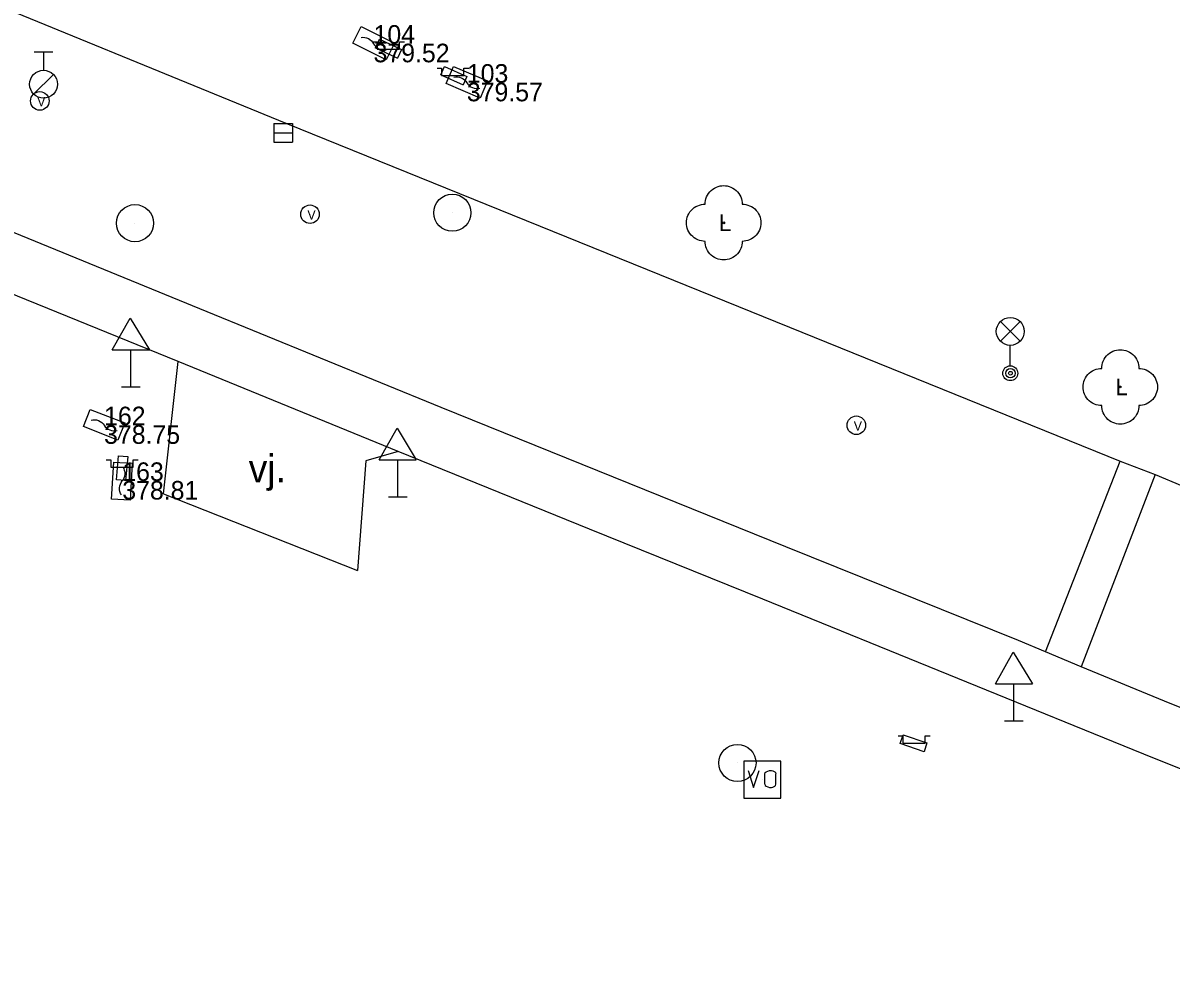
# Model space of a CAD drawing. Extents: x -836568 to -836015, y -1070547 to -1070212.
# Drawn here: x -836329.46 to -836298.57, y -1070441.99 to -1070416.28 of the extents above; entities that cross this region are included whole.
import ezdxf

# ---------------------------------------------------------------- set-up
doc = ezdxf.new("R2010")
doc.units = 0
for name, color, linetype in [('BodPole_mer', 7, 'Continuous'), ('BodPole_popis', 7, 'Continuous'), ('Doprava_body', 7, 'Continuous'), ('Doprava_hranice', 7, 'Continuous'), ('Doprava_kody', 7, 'Continuous'), ('PovrZnIS_body', 7, 'Continuous'), ('PovrZnIS_hranice', 7, 'Continuous'), ('PovrZnIS_kody', 7, 'Continuous'), ('Zelen_body', 7, 'Continuous')]:
    doc.layers.add(name, color=color, linetype=linetype)

msp = doc.modelspace()

# ---------------------------------------------------------------- linework, layer by layer
at = {"layer": 'BodPole_mer'}
for p, q in [((-836320.03, -1070416.84), (-836320.03, -1070416.84)), ((-836319.87, -1070416.72), (-836319.87, -1070416.72)), ((-836319.87, -1070416.72), (-836319.87, -1070416.72)), ((-836319.98, -1070416.95), (-836319.98, -1070416.95)), ((-836319.98, -1070416.95), (-836319.98, -1070416.95)), ((-836319.28, -1070417), (-836319.28, -1070417)), ((-836319.28, -1070417), (-836319.28, -1070417)), ((-836319.39, -1070417.23), (-836319.39, -1070417.23)), ((-836319.39, -1070417.23), (-836319.39, -1070417.23)), ((-836318.12, -1070417.45), (-836318.12, -1070417.45)), ((-836318.12, -1070417.45), (-836318.12, -1070417.45)), ((-836318.22, -1070417.68), (-836318.22, -1070417.68)), ((-836318.22, -1070417.68), (-836318.22, -1070417.68)), ((-836317.52, -1070417.72), (-836317.52, -1070417.72)), ((-836317.52, -1070417.72), (-836317.52, -1070417.72)), ((-836328.91, -1070417.93), (-836328.91, -1070417.93)), ((-836317.62, -1070417.95), (-836317.62, -1070417.95)), ((-836317.62, -1070417.95), (-836317.62, -1070417.95)), ((-836317.52, -1070417.89), (-836317.52, -1070417.89)), ((-836329.01, -1070418.38), (-836329.01, -1070418.38)), ((-836322.39, -1070418.98), (-836322.39, -1070418.98)), ((-836322.46, -1070419.24), (-836322.46, -1070419.24)), ((-836321.74, -1070421.43), (-836321.74, -1070421.43)), ((-836317.91, -1070421.39), (-836317.91, -1070421.39)), ((-836326.45, -1070421.67), (-836326.45, -1070421.67)), ((-836310.61, -1070421.66), (-836310.61, -1070421.66)), ((-836329.32, -1070422.08), (-836329.32, -1070422.08)), ((-836311.25, -1070423.49), (-836311.25, -1070423.49)), ((-836324.7, -1070423.98), (-836324.7, -1070423.98)), ((-836325.29, -1070425.39), (-836325.29, -1070425.39)), ((-836302.9, -1070425.71), (-836302.9, -1070425.71)), ((-836326.56, -1070426.08), (-836326.56, -1070426.08)), ((-836299.94, -1070426.08), (-836299.94, -1070426.08)), ((-836318.21, -1070426.63), (-836318.21, -1070426.63)), ((-836327.28, -1070427.11), (-836327.28, -1070427.11)), ((-836307.04, -1070427.11), (-836307.04, -1070427.11)), ((-836326.89, -1070427.93), (-836326.89, -1070427.93)), ((-836326.89, -1070427.93), (-836326.89, -1070427.93)), ((-836326.64, -1070427.95), (-836326.64, -1070427.95)), ((-836326.64, -1070427.95), (-836326.64, -1070427.95)), ((-836319.37, -1070427.82), (-836319.37, -1070427.82)), ((-836320.24, -1070428.07), (-836320.24, -1070428.07)), ((-836299.94, -1070428.08), (-836299.94, -1070428.08)), ((-836326.95, -1070428.58), (-836326.95, -1070428.58)), ((-836326.95, -1070428.58), (-836326.95, -1070428.58)), ((-836326.79, -1070428.61), (-836326.79, -1070428.61)), ((-836326.7, -1070428.6), (-836326.7, -1070428.6)), ((-836326.7, -1070428.6), (-836326.7, -1070428.6)), ((-836313.57, -1070428.51), (-836313.57, -1070428.51)), ((-836299, -1070428.44), (-836299, -1070428.44)), ((-836325.68, -1070428.96), (-836325.68, -1070428.96)), ((-836319.38, -1070429.04), (-836319.38, -1070429.04)), ((-836314.22, -1070429.91), (-836314.22, -1070429.91)), ((-836308.94, -1070430.38), (-836308.94, -1070430.38)), ((-836320.46, -1070431.02), (-836320.46, -1070431.02)), ((-836309.56, -1070431.79), (-836309.56, -1070431.79)), ((-836302.68, -1070432.9), (-836302.68, -1070432.9)), ((-836301.95, -1070433.21), (-836301.95, -1070433.21)), ((-836300.99, -1070433.61), (-836300.99, -1070433.61)), ((-836298.75, -1070434.54), (-836298.75, -1070434.54)), ((-836302.8, -1070435.07), (-836302.8, -1070435.07)), ((-836305.86, -1070435.68), (-836305.86, -1070435.68)), ((-836305.86, -1070435.68), (-836305.86, -1070435.68)), ((-836305.78, -1070435.44), (-836305.78, -1070435.44)), ((-836305.78, -1070435.44), (-836305.78, -1070435.44)), ((-836305.14, -1070435.66), (-836305.14, -1070435.66)), ((-836305.14, -1070435.66), (-836305.14, -1070435.66)), ((-836305.22, -1070435.9), (-836305.22, -1070435.9)), ((-836305.22, -1070435.9), (-836305.22, -1070435.9)), ((-836310.24, -1070436.2), (-836310.24, -1070436.2)), ((-836299.06, -1070436.06), (-836299.06, -1070436.06)), ((-836309.57, -1070436.65), (-836309.57, -1070436.65))]:
    msp.add_line(p, q, dxfattribs=at)
at = {"layer": 'Doprava_body'}
for p, q in [((-836327.06, -1070425.08), (-836326.579, -1070424.226)), ((-836326.579, -1070424.226), (-836326.06, -1070425.08)), ((-836327.06, -1070425.08), (-836326.06, -1070425.08)), ((-836326.56, -1070426.08), (-836326.56, -1070425.08)), ((-836326.81, -1070426.08), (-836326.31, -1070426.08)), ((-836319.88, -1070428.04), (-836319.399, -1070427.186)), ((-836319.399, -1070427.186), (-836318.88, -1070428.04)), ((-836319.88, -1070428.04), (-836318.88, -1070428.04)), ((-836319.38, -1070429.04), (-836319.38, -1070428.04)), ((-836319.63, -1070429.04), (-836319.13, -1070429.04)), ((-836303.3, -1070434.07), (-836302.819, -1070433.216)), ((-836302.819, -1070433.216), (-836302.3, -1070434.07)), ((-836303.3, -1070434.07), (-836302.3, -1070434.07)), ((-836302.8, -1070435.07), (-836302.8, -1070434.07)), ((-836303.05, -1070435.07), (-836302.55, -1070435.07))]:
    msp.add_line(p, q, dxfattribs=at)
at = {"layer": 'Doprava_hranice'}
for p, q in [((-836325.68, -1070428.96), (-836325.29, -1070425.39)), ((-836301.95, -1070433.21), (-836299.94, -1070428.08)), ((-836299, -1070428.44), (-836300.99, -1070433.61)), ((-836325.68, -1070428.96), (-836320.46, -1070431.02))]:
    msp.add_line(p, q, dxfattribs=at)
for points in [[(-836294.78, -1070436.14), (-836298.75, -1070434.54), (-836300.99, -1070433.61), (-836301.95, -1070433.21), (-836302.68, -1070432.9), (-836308.94, -1070430.38), (-836313.57, -1070428.51), (-836318.21, -1070426.63), (-836324.7, -1070423.98), (-836329.32, -1070422.08), (-836333.96, -1070420.19), (-836342.84, -1070416.58), (-836353.67, -1070412.18), (-836369.06, -1070405.92), (-836381.28, -1070400.95), (-836385.01, -1070399.41), (-836387.75, -1070398.25), (-836390.49, -1070397.04), (-836393.21, -1070395.81), (-836395.03, -1070394.97), (-836397.75, -1070393.68), (-836399.24, -1070392.97)], [(-836351.68, -1070407.06), (-836340.95, -1070411.41), (-836331.95, -1070415.06), (-836322.39, -1070418.98), (-836311.25, -1070423.49), (-836299.94, -1070428.08), (-836299, -1070428.44), (-836298.27, -1070428.74)], [(-836282.83, -1070440.54), (-836283.39, -1070441.99), (-836288.97, -1070439.98), (-836292.82, -1070438.51), (-836295.89, -1070437.33), (-836299.06, -1070436.06), (-836309.56, -1070431.79), (-836314.22, -1070429.91), (-836319.37, -1070427.82), (-836325.29, -1070425.39), (-836329.9, -1070423.52), (-836331.04, -1070426.22), (-836335.67, -1070424.36), (-836334.55, -1070421.64), (-836343.54, -1070417.97), (-836354.29, -1070413.6)], [(-836319.37, -1070427.82), (-836320.24, -1070428.07), (-836320.46, -1070431.02)]]:
    msp.add_lwpolyline(points, dxfattribs=at)
at = {"layer": 'PovrZnIS_body'}
for p, q in [((-836320.588, -1070416.827), (-836320.365, -1070416.38)), ((-836320.365, -1070416.38), (-836319.47, -1070416.827)), ((-836319.694, -1070417.274), (-836320.588, -1070416.827)), ((-836319.47, -1070416.827), (-836319.694, -1070417.274)), ((-836329.16, -1070417.055), (-836328.66, -1070417.055)), ((-836328.91, -1070417.055), (-836328.91, -1070417.555)), ((-836318.078, -1070417.911), (-836317.882, -1070417.451)), ((-836317.882, -1070417.451), (-836316.962, -1070417.843)), ((-836328.645, -1070417.665), (-836329.175, -1070418.195)), ((-836317.158, -1070418.303), (-836318.078, -1070417.911)), ((-836316.962, -1070417.843), (-836317.158, -1070418.303)), ((-836322.71, -1070418.99), (-836322.21, -1070418.99)), ((-836322.71, -1070418.99), (-836322.71, -1070419.49)), ((-836322.21, -1070418.99), (-836322.21, -1070419.49)), ((-836322.71, -1070419.24), (-836322.21, -1070419.24)), ((-836322.71, -1070419.49), (-836322.21, -1070419.49)), ((-836303.165, -1070424.85), (-836302.635, -1070424.32)), ((-836303.165, -1070424.32), (-836302.635, -1070424.85)), ((-836302.9, -1070425.51), (-836302.9, -1070424.96)), ((-836327.837, -1070427.147), (-836327.654, -1070426.682)), ((-836327.654, -1070426.682), (-836326.723, -1070427.047)), ((-836326.723, -1070427.047), (-836326.906, -1070427.513)), ((-836326.906, -1070427.513), (-836327.837, -1070427.147)), ((-836327.082, -1070429.098), (-836327.021, -1070428.1)), ((-836327.021, -1070428.1), (-836326.522, -1070428.13)), ((-836326.522, -1070428.13), (-836326.583, -1070429.128)), ((-836326.583, -1070429.128), (-836327.082, -1070429.098)), ((-836309.07, -1070436.15), (-836310.07, -1070436.15)), ((-836310.07, -1070436.15), (-836310.07, -1070437.15)), ((-836309.07, -1070437.15), (-836309.07, -1070436.15)), ((-836310.07, -1070437.15), (-836309.07, -1070437.15))]:
    msp.add_line(p, q, dxfattribs=at)
for points in [[(-836320.367, -1070416.671), (-836320.319, -1070416.667), (-836320.269, -1070416.669), (-836320.219, -1070416.68), (-836320.17, -1070416.7), (-836320.126, -1070416.727), (-836320.087, -1070416.76), (-836320.055, -1070416.799), (-836320.03, -1070416.84)], [(-836320.03, -1070416.84), (-836320.005, -1070416.881), (-836319.973, -1070416.919), (-836319.935, -1070416.953), (-836319.89, -1070416.98), (-836319.842, -1070416.999), (-836319.792, -1070417.01), (-836319.742, -1070417.013), (-836319.695, -1070417.008)], [(-836317.867, -1070417.742), (-836317.819, -1070417.735), (-836317.769, -1070417.734), (-836317.718, -1070417.742), (-836317.669, -1070417.759), (-836317.623, -1070417.783), (-836317.582, -1070417.814), (-836317.547, -1070417.85), (-836317.52, -1070417.89)], [(-836317.52, -1070417.89), (-836317.493, -1070417.93), (-836317.459, -1070417.966), (-836317.418, -1070417.997), (-836317.372, -1070418.021), (-836317.323, -1070418.037), (-836317.272, -1070418.045), (-836317.222, -1070418.045), (-836317.175, -1070418.037)], [(-836327.63, -1070426.972), (-836327.583, -1070426.963), (-836327.533, -1070426.961), (-836327.482, -1070426.968), (-836327.432, -1070426.983), (-836327.386, -1070427.006), (-836327.344, -1070427.036), (-836327.308, -1070427.071), (-836327.28, -1070427.11)], [(-836327.28, -1070427.11), (-836327.252, -1070427.149), (-836327.216, -1070427.184), (-836327.175, -1070427.214), (-836327.128, -1070427.237), (-836327.079, -1070427.252), (-836327.028, -1070427.258), (-836326.978, -1070427.256), (-836326.931, -1070427.247)], [(-836326.79, -1070428.61), (-836326.762, -1070428.571), (-836326.739, -1070428.527), (-836326.724, -1070428.478), (-836326.716, -1070428.427), (-836326.717, -1070428.375), (-836326.727, -1070428.324), (-836326.744, -1070428.278), (-836326.767, -1070428.236)], [(-836326.813, -1070428.986), (-836326.836, -1070428.944), (-836326.853, -1070428.897), (-836326.863, -1070428.846), (-836326.864, -1070428.794), (-836326.856, -1070428.743), (-836326.841, -1070428.694), (-836326.818, -1070428.649), (-836326.79, -1070428.61)], [(-836309.955, -1070436.407), (-836309.805, -1070436.857)], [(-836309.805, -1070436.857), (-836309.655, -1070436.407)], [(-836309.503, -1070436.491), (-836309.493, -1070436.461), (-836309.47, -1070436.438), (-836309.424, -1070436.417), (-836309.379, -1070436.407), (-836309.319, -1070436.407), (-836309.29, -1070436.415), (-836309.233, -1070436.44), (-836309.213, -1070436.461), (-836309.203, -1070436.491)], [(-836309.503, -1070436.772), (-836309.503, -1070436.491)], [(-836309.203, -1070436.772), (-836309.203, -1070436.491)], [(-836309.503, -1070436.772), (-836309.493, -1070436.803), (-836309.47, -1070436.825), (-836309.424, -1070436.847), (-836309.379, -1070436.857), (-836309.319, -1070436.857), (-836309.29, -1070436.849), (-836309.233, -1070436.823), (-836309.213, -1070436.803), (-836309.203, -1070436.772)]]:
    msp.add_lwpolyline(points, dxfattribs=at)
for centre, radius in [((-836328.91, -1070417.93), 0.375), ((-836329.01, -1070418.38), 0.25), ((-836317.91, -1070421.39), 0.5), ((-836326.45, -1070421.67), 0.5), ((-836321.74, -1070421.43), 0.25), ((-836307.04, -1070427.11), 0.25), ((-836310.24, -1070436.2), 0.5)]:
    msp.add_circle(centre, radius, dxfattribs=at)
for centre, major_axis in [((-836302.9, -1070424.585), (0.375, 0)), ((-836302.9, -1070425.71), (0.2, 0)), ((-836302.896, -1070425.71), (0.125, 0)), ((-836302.896, -1070425.71), (0.05, 0))]:
    msp.add_ellipse(centre, major_axis=major_axis, ratio=0.999998, dxfattribs=at)
at = {"layer": 'PovrZnIS_hranice'}
for p, q in [((-836319.98, -1070416.95), (-836319.39, -1070417.23)), ((-836319.98, -1070416.95), (-836319.39, -1070417.23)), ((-836318.22, -1070417.68), (-836317.62, -1070417.95)), ((-836318.22, -1070417.68), (-836317.62, -1070417.95)), ((-836326.64, -1070427.95), (-836326.7, -1070428.6)), ((-836326.64, -1070427.95), (-836326.7, -1070428.6)), ((-836305.78, -1070435.44), (-836305.14, -1070435.66)), ((-836305.78, -1070435.44), (-836305.14, -1070435.66))]:
    msp.add_line(p, q, dxfattribs=at)
for points in [[(-836319.98, -1070416.95), (-836319.87, -1070416.72), (-836319.28, -1070417), (-836319.39, -1070417.23)], [(-836319.98, -1070416.95), (-836319.87, -1070416.72), (-836319.28, -1070417), (-836319.39, -1070417.23)], [(-836318.22, -1070417.68), (-836318.12, -1070417.45), (-836317.52, -1070417.72), (-836317.62, -1070417.95)], [(-836318.22, -1070417.68), (-836318.12, -1070417.45), (-836317.52, -1070417.72), (-836317.62, -1070417.95)], [(-836326.7, -1070428.6), (-836326.95, -1070428.58), (-836326.89, -1070427.93), (-836326.64, -1070427.95)], [(-836326.7, -1070428.6), (-836326.95, -1070428.58), (-836326.89, -1070427.93), (-836326.64, -1070427.95)], [(-836305.14, -1070435.66), (-836305.22, -1070435.9), (-836305.86, -1070435.68), (-836305.78, -1070435.44)], [(-836305.14, -1070435.66), (-836305.22, -1070435.9), (-836305.86, -1070435.68), (-836305.78, -1070435.44)]]:
    msp.add_lwpolyline(points, dxfattribs=at)
at = {"layer": 'PovrZnIS_kody'}
for p, q in [((-836320.051, -1070416.79), (-836319.93, -1070416.79)), ((-836320.051, -1070416.79), (-836319.93, -1070416.79)), ((-836319.93, -1070416.79), (-836319.93, -1070416.99)), ((-836319.93, -1070416.79), (-836319.93, -1070416.99)), ((-836319.33, -1070416.99), (-836319.33, -1070416.79)), ((-836319.33, -1070416.79), (-836319.196, -1070416.79)), ((-836319.33, -1070416.99), (-836319.33, -1070416.79)), ((-836319.33, -1070416.79), (-836319.196, -1070416.79)), ((-836319.93, -1070416.99), (-836319.33, -1070416.99)), ((-836319.93, -1070416.99), (-836319.33, -1070416.99)), ((-836318.321, -1070417.5), (-836318.2, -1070417.5)), ((-836318.321, -1070417.5), (-836318.2, -1070417.5)), ((-836318.2, -1070417.5), (-836318.2, -1070417.7)), ((-836318.2, -1070417.5), (-836318.2, -1070417.7)), ((-836318.2, -1070417.7), (-836317.6, -1070417.7)), ((-836318.2, -1070417.7), (-836317.6, -1070417.7)), ((-836317.6, -1070417.7), (-836317.6, -1070417.5)), ((-836317.6, -1070417.5), (-836317.466, -1070417.5)), ((-836317.6, -1070417.7), (-836317.6, -1070417.5)), ((-836317.6, -1070417.5), (-836317.466, -1070417.5)), ((-836327.221, -1070428.04), (-836327.1, -1070428.04)), ((-836327.221, -1070428.04), (-836327.1, -1070428.04)), ((-836327.1, -1070428.04), (-836327.1, -1070428.24)), ((-836327.1, -1070428.04), (-836327.1, -1070428.24)), ((-836327.1, -1070428.24), (-836326.5, -1070428.24)), ((-836327.1, -1070428.24), (-836326.5, -1070428.24)), ((-836326.5, -1070428.24), (-836326.5, -1070428.04)), ((-836326.5, -1070428.04), (-836326.366, -1070428.04)), ((-836326.5, -1070428.24), (-836326.5, -1070428.04)), ((-836326.5, -1070428.04), (-836326.366, -1070428.04)), ((-836305.911, -1070435.47), (-836305.79, -1070435.47)), ((-836305.911, -1070435.47), (-836305.79, -1070435.47)), ((-836305.79, -1070435.47), (-836305.79, -1070435.67)), ((-836305.79, -1070435.47), (-836305.79, -1070435.67)), ((-836305.79, -1070435.67), (-836305.19, -1070435.67)), ((-836305.79, -1070435.67), (-836305.19, -1070435.67)), ((-836305.19, -1070435.67), (-836305.19, -1070435.47)), ((-836305.19, -1070435.47), (-836305.056, -1070435.47)), ((-836305.19, -1070435.67), (-836305.19, -1070435.47)), ((-836305.19, -1070435.47), (-836305.056, -1070435.47))]:
    msp.add_line(p, q, dxfattribs=at)
at = {"layer": 'Zelen_body'}
for p, q in [((-836310.61, -1070421.66), (-836310.61, -1070421.66)), ((-836299.94, -1070426.08), (-836299.94, -1070426.08))]:
    msp.add_line(p, q, dxfattribs=at)
for points in [[(-836311.11, -1070421.16), (-836311.108, -1070421.112), (-836311.1, -1070421.063), (-836311.088, -1070421.013), (-836311.07, -1070420.964), (-836311.046, -1070420.915), (-836311.017, -1070420.869), (-836310.983, -1070420.826), (-836310.944, -1070420.787), (-836310.901, -1070420.753), (-836310.855, -1070420.724), (-836310.806, -1070420.7), (-836310.757, -1070420.682), (-836310.707, -1070420.67), (-836310.658, -1070420.662), (-836310.61, -1070420.66), (-836310.562, -1070420.662), (-836310.513, -1070420.67), (-836310.463, -1070420.682), (-836310.414, -1070420.7), (-836310.365, -1070420.724), (-836310.319, -1070420.753), (-836310.276, -1070420.787), (-836310.237, -1070420.826), (-836310.203, -1070420.869), (-836310.174, -1070420.915), (-836310.15, -1070420.964), (-836310.132, -1070421.013), (-836310.12, -1070421.063), (-836310.112, -1070421.112), (-836310.11, -1070421.16)], [(-836311.11, -1070422.16), (-836311.158, -1070422.158), (-836311.207, -1070422.15), (-836311.257, -1070422.138), (-836311.306, -1070422.12), (-836311.355, -1070422.096), (-836311.401, -1070422.067), (-836311.444, -1070422.033), (-836311.483, -1070421.994), (-836311.517, -1070421.951), (-836311.546, -1070421.905), (-836311.57, -1070421.856), (-836311.588, -1070421.807), (-836311.6, -1070421.757), (-836311.608, -1070421.708), (-836311.61, -1070421.66), (-836311.608, -1070421.612), (-836311.6, -1070421.563), (-836311.588, -1070421.513), (-836311.57, -1070421.464), (-836311.546, -1070421.415), (-836311.517, -1070421.369), (-836311.483, -1070421.326), (-836311.444, -1070421.287), (-836311.401, -1070421.253), (-836311.355, -1070421.224), (-836311.306, -1070421.2), (-836311.257, -1070421.182), (-836311.207, -1070421.17), (-836311.158, -1070421.162), (-836311.11, -1070421.16)], [(-836310.11, -1070421.16), (-836310.062, -1070421.162), (-836310.013, -1070421.17), (-836309.963, -1070421.182), (-836309.914, -1070421.2), (-836309.865, -1070421.224), (-836309.819, -1070421.253), (-836309.776, -1070421.287), (-836309.737, -1070421.326), (-836309.703, -1070421.369), (-836309.674, -1070421.415), (-836309.65, -1070421.464), (-836309.632, -1070421.513), (-836309.62, -1070421.563), (-836309.612, -1070421.612), (-836309.61, -1070421.66), (-836309.612, -1070421.708), (-836309.62, -1070421.757), (-836309.632, -1070421.807), (-836309.65, -1070421.856), (-836309.674, -1070421.905), (-836309.703, -1070421.951), (-836309.737, -1070421.994), (-836309.776, -1070422.033), (-836309.819, -1070422.067), (-836309.865, -1070422.096), (-836309.914, -1070422.12), (-836309.963, -1070422.138), (-836310.013, -1070422.15), (-836310.062, -1070422.158), (-836310.11, -1070422.16)], [(-836310.11, -1070422.16), (-836310.112, -1070422.208), (-836310.12, -1070422.257), (-836310.132, -1070422.307), (-836310.15, -1070422.356), (-836310.174, -1070422.405), (-836310.203, -1070422.451), (-836310.237, -1070422.494), (-836310.276, -1070422.533), (-836310.319, -1070422.567), (-836310.365, -1070422.596), (-836310.414, -1070422.62), (-836310.463, -1070422.638), (-836310.513, -1070422.65), (-836310.562, -1070422.658), (-836310.61, -1070422.66), (-836310.658, -1070422.658), (-836310.707, -1070422.65), (-836310.757, -1070422.638), (-836310.806, -1070422.62), (-836310.855, -1070422.596), (-836310.901, -1070422.567), (-836310.944, -1070422.533), (-836310.983, -1070422.494), (-836311.017, -1070422.451), (-836311.046, -1070422.405), (-836311.07, -1070422.356), (-836311.088, -1070422.307), (-836311.1, -1070422.257), (-836311.108, -1070422.208), (-836311.11, -1070422.16)], [(-836300.44, -1070425.58), (-836300.438, -1070425.532), (-836300.43, -1070425.483), (-836300.418, -1070425.433), (-836300.4, -1070425.384), (-836300.376, -1070425.335), (-836300.347, -1070425.289), (-836300.313, -1070425.246), (-836300.274, -1070425.207), (-836300.231, -1070425.173), (-836300.185, -1070425.144), (-836300.136, -1070425.12), (-836300.087, -1070425.102), (-836300.037, -1070425.09), (-836299.988, -1070425.082), (-836299.94, -1070425.08), (-836299.892, -1070425.082), (-836299.843, -1070425.09), (-836299.793, -1070425.102), (-836299.744, -1070425.12), (-836299.695, -1070425.144), (-836299.649, -1070425.173), (-836299.606, -1070425.207), (-836299.567, -1070425.246), (-836299.533, -1070425.289), (-836299.504, -1070425.335), (-836299.48, -1070425.384), (-836299.462, -1070425.433), (-836299.45, -1070425.483), (-836299.442, -1070425.532), (-836299.44, -1070425.58)], [(-836300.44, -1070426.58), (-836300.488, -1070426.578), (-836300.537, -1070426.57), (-836300.587, -1070426.558), (-836300.636, -1070426.54), (-836300.685, -1070426.516), (-836300.731, -1070426.487), (-836300.774, -1070426.453), (-836300.813, -1070426.414), (-836300.847, -1070426.371), (-836300.876, -1070426.325), (-836300.9, -1070426.276), (-836300.918, -1070426.227), (-836300.93, -1070426.177), (-836300.938, -1070426.128), (-836300.94, -1070426.08), (-836300.938, -1070426.032), (-836300.93, -1070425.983), (-836300.918, -1070425.933), (-836300.9, -1070425.884), (-836300.876, -1070425.835), (-836300.847, -1070425.789), (-836300.813, -1070425.746), (-836300.774, -1070425.707), (-836300.731, -1070425.673), (-836300.685, -1070425.644), (-836300.636, -1070425.62), (-836300.587, -1070425.602), (-836300.537, -1070425.59), (-836300.488, -1070425.582), (-836300.44, -1070425.58)], [(-836299.44, -1070425.58), (-836299.392, -1070425.582), (-836299.343, -1070425.59), (-836299.293, -1070425.602), (-836299.244, -1070425.62), (-836299.195, -1070425.644), (-836299.149, -1070425.673), (-836299.106, -1070425.707), (-836299.067, -1070425.746), (-836299.033, -1070425.789), (-836299.004, -1070425.835), (-836298.98, -1070425.884), (-836298.962, -1070425.933), (-836298.95, -1070425.983), (-836298.942, -1070426.032), (-836298.94, -1070426.08), (-836298.942, -1070426.128), (-836298.95, -1070426.177), (-836298.962, -1070426.227), (-836298.98, -1070426.276), (-836299.004, -1070426.325), (-836299.033, -1070426.371), (-836299.067, -1070426.414), (-836299.106, -1070426.453), (-836299.149, -1070426.487), (-836299.195, -1070426.516), (-836299.244, -1070426.54), (-836299.293, -1070426.558), (-836299.343, -1070426.57), (-836299.392, -1070426.578), (-836299.44, -1070426.58)], [(-836299.44, -1070426.58), (-836299.442, -1070426.628), (-836299.45, -1070426.677), (-836299.462, -1070426.727), (-836299.48, -1070426.776), (-836299.504, -1070426.825), (-836299.533, -1070426.871), (-836299.567, -1070426.914), (-836299.606, -1070426.953), (-836299.649, -1070426.987), (-836299.695, -1070427.016), (-836299.744, -1070427.04), (-836299.793, -1070427.058), (-836299.843, -1070427.07), (-836299.892, -1070427.078), (-836299.94, -1070427.08), (-836299.988, -1070427.078), (-836300.037, -1070427.07), (-836300.087, -1070427.058), (-836300.136, -1070427.04), (-836300.185, -1070427.016), (-836300.231, -1070426.987), (-836300.274, -1070426.953), (-836300.313, -1070426.914), (-836300.347, -1070426.871), (-836300.376, -1070426.825), (-836300.4, -1070426.776), (-836300.418, -1070426.727), (-836300.43, -1070426.677), (-836300.438, -1070426.628), (-836300.44, -1070426.58)]]:
    msp.add_lwpolyline(points, dxfattribs=at)
for centre in [(-836310.61, -1070421.66), (-836299.94, -1070426.08)]:
    msp.add_ellipse(centre, major_axis=(0.025, 0), ratio=0.999997, dxfattribs=at)

# ---------------------------------------------------------------- texts
at = {"layer": 'BodPole_popis'}
for s, p in [('104', (-836320.03, -1070416.84)), ('379.52', (-836320.03, -1070417.34)), ('103', (-836317.52, -1070417.89)), ('379.57', (-836317.52, -1070418.39)), ('162', (-836327.28, -1070427.11)), ('378.75', (-836327.28, -1070427.61)), ('163', (-836326.79, -1070428.61)), ('378.81', (-836326.79, -1070429.11))]:
    msp.add_text(s, height=0.5, dxfattribs=at).set_placement(p)
at = {"layer": 'Doprava_kody'}
msp.add_text('vj.', height=0.75, dxfattribs=at).set_placement((-836323.39, -1070428.65))
at = {"layer": 'PovrZnIS_body'}
for p in [(-836329.081, -1070418.523), (-836321.811, -1070421.573), (-836307.111, -1070427.253)]:
    msp.add_text('V', height=0.25, dxfattribs=at).set_placement(p)
at = {"layer": 'Zelen_body'}
for p in [(-836310.741, -1070421.885), (-836300.071, -1070426.305)]:
    msp.add_text('L', height=0.45, dxfattribs=at).set_placement(p)

doc.saveas('drawing.dxf')
